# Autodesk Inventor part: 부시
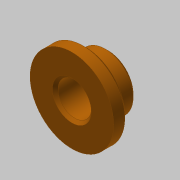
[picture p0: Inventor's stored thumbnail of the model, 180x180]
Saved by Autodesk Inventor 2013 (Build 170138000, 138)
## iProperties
Created: 2016-02
Part Number: 부시
Material: 스테인리스강
Document SubType Name: Modeling
Designer: mduedu
Density: 8.08 g/cm^3
Author: mduedu
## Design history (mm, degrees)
sketch "스케치1"
  geometry: C1 r 15 at (0, 0); 1 further point
  constraints: 1 centre point, 1 coincident
  dimensions: "d0" = 30 diameter of C1
extrude "돌출1" new body sketch "스케치1" distance "d1" = 5; taper "d2" = 0 deg
sketch "스케치2"
  geometry: C1 r 10 at (0, 0); 1 further point
  constraints: 1 centre point, 1 coincident
  dimensions: "d3" = 20 diameter of C1
extrude "돌출2" join sketch "스케치2" distance "d4" = 8; taper "d5" = 0 deg
hole "구멍1" diameter "d8" = 12; stored, may be unused: countersink angle "d12" = 90 deg, drill point angle "d14" = 118 deg; dims "d9" = 6, "d10" = 4, "d11" = 2, "d13" = 8, "d15" = 10, "d16" = 10
chamfer "모따기1" distance "d17" = 1; stored, may be unused: second distance "d18" = 2, angle "d19" = 45 deg
chamfer "모따기2" distance "d20" = 1; stored, may be unused: second distance "d21" = 2, angle "d22" = 45 deg
chamfer "모따기3" distance "d23" = 1; stored, may be unused: second distance "d24" = 2, angle "d25" = 45 deg
node "솔리드1"
